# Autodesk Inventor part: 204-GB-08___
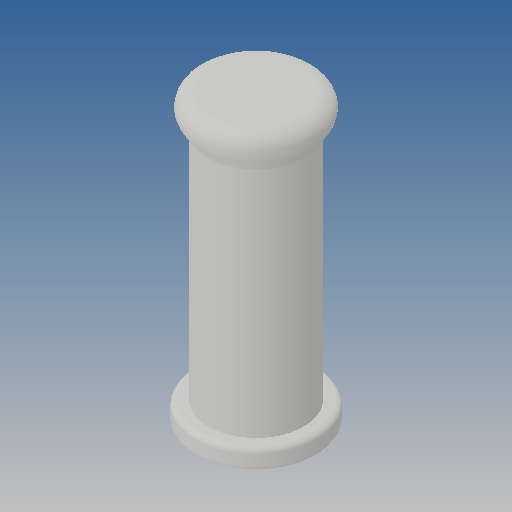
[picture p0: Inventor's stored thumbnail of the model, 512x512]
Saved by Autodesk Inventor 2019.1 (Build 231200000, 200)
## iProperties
Created: 2010-06
Part Number: 204-GB-08___
Material: Ogólny
Document SubType Name: Modeling
Designer: CADENGINEERING4
Density: 1 g/cm^3
Appearance: Domyślna
Author: CADENGINEERING4
Revision Number: ANY
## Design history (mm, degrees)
feature "NONE"
node "Bryła1"
